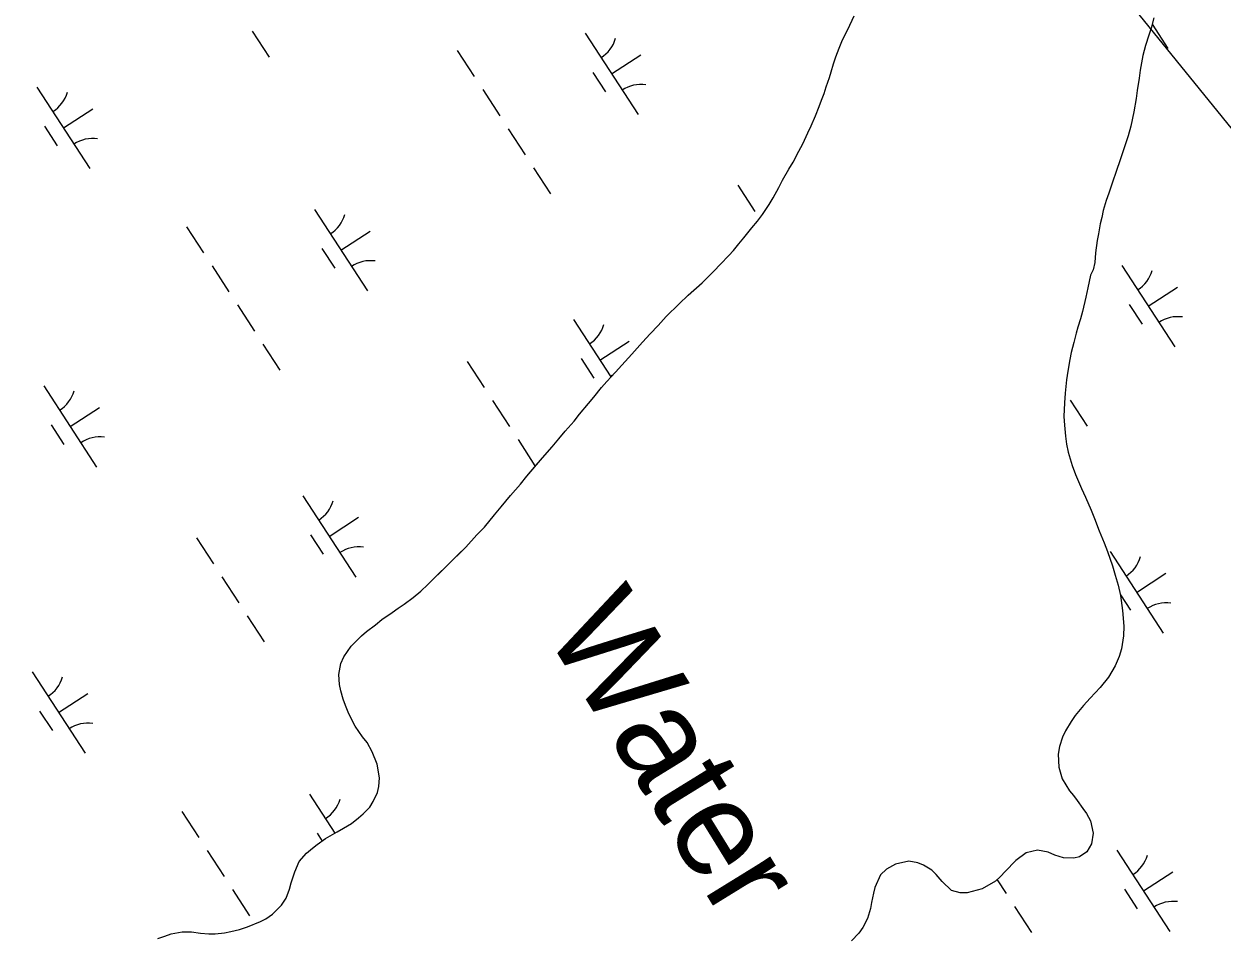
# Model space of a CAD drawing. Extents: x 3953924 to 3974542, y 193747 to 216192.
# Drawn here: x 3962480 to 3963097, y 211218 to 211687 of the extents above; entities that cross this region are included whole.
import ezdxf

# ---------------------------------------------------------------- set-up
doc = ezdxf.new("R2010")
doc.units = 0
for name, color, linetype in [('V-GRID-MAJR', 7, 'Continuous'), ('V-RIVR-IDEN', 7, 'Continuous'), ('V-TOPO-SHOR', 7, 'Continuous'), ('V-UTIL-LINE', 7, 'Continuous'), ('V-WETL-SWMP', 7, 'Continuous')]:
    doc.layers.add(name, color=color, linetype=linetype)

msp = doc.modelspace()

# ---------------------------------------------------------------- linework, layer by layer
at = {"layer": 'V-GRID-MAJR'}
msp.add_spline([(3962589.82, 201207.1), (3962493.71, 206368.64), (3962380.88, 212428.56), (3962369.25, 213053.16)], degree=3, dxfattribs=at)
at = {"layer": 'V-TOPO-SHOR'}
for points in [[(3962864.13, 211594.33), (3962866.18, 211597.83), (3962869.06, 211603.21), (3962870.97, 211606.98), (3962874.12, 211612.49), (3962876.45, 211616.25), (3962879.33, 211621.76), (3962881.38, 211625.66), (3962883.99, 211631.32), (3962885.77, 211634.95), (3962887.97, 211640.06), (3962889.77, 211644.91), (3962891, 211648.14), (3962892.38, 211651.51), (3962893.35, 211655.01), (3962895.15, 211659.72), (3962895.98, 211662.68), (3962897.22, 211666.73), (3962898.33, 211670.36), (3962900.12, 211674.8), (3962901.91, 211679.11), (3962904.52, 211684.49), (3962907.81, 211691.49)], [(3963062.14, 211690.44), (3963060.75, 211685.19), (3963059.5, 211681.55), (3963057.84, 211676.3), (3963056.45, 211671.04), (3963055.75, 211667.4), (3963055.04, 211663.63), (3963054.61, 211659.44), (3963053.62, 211653.1), (3963053.04, 211648.92), (3963051.91, 211642.05), (3963050.23, 211634.77), (3963048.98, 211629.78), (3963046.49, 211622.51), (3963044.97, 211617.93), (3963042.62, 211610.79), (3963041.1, 211606.35), (3963038.9, 211600.15), (3963037.65, 211596.38), (3963036.13, 211591.26), (3963035.29, 211587.76), (3963034.59, 211584.39), (3963033.6, 211579.26), (3963033.04, 211575.76), (3963032.18, 211569.42), (3963031.74, 211564.56), (3963030.9, 211560.79), (3963029.52, 211557.96), (3963028.12, 211551.49), (3963027.14, 211546.64), (3963025.47, 211539.36), (3963024.36, 211535.59), (3963022.98, 211531.14), (3963022.14, 211528.18), (3963020.89, 211523.33)], [(3962549.32, 211216.38), (3962552.98, 211217.7), (3962556.23, 211218.76), (3962561.77, 211219.8), (3962566.63, 211219.89), (3962571.22, 211219.18), (3962575.53, 211218.88), (3962578.78, 211218.86), (3962583.64, 211219.36), (3962586.89, 211220.01), (3962591.35, 211221.05), (3962595.54, 211222.37), (3962602.18, 211225.15), (3962604.89, 211226.49), (3962608.29, 211229.02), (3962612.91, 211233.58), (3962615.37, 211237.21), (3962617.03, 211241.92), (3962618, 211245.02), (3962619.8, 211250.81), (3962622.13, 211256.06), (3962625.81, 211260.35), (3962628.94, 211262.89), (3962631.38, 211264.77), (3962635.59, 211267.84), (3962641.69, 211271.3), (3962644.81, 211273.17), (3962649.02, 211275.7), (3962652.69, 211278.64), (3962655, 211280.65), (3962658.4, 211284.14), (3962660.18, 211286.96), (3962662.37, 211291.53), (3962663.07, 211294.63), (3962663.51, 211299.22), (3962662.21, 211306.25), (3962659.7, 211312.48), (3962657.04, 211317.36), (3962654.76, 211320.35), (3962650.89, 211325.78), (3962647.7, 211332.15), (3962645.97, 211336.35), (3962644.78, 211339.6), (3962643.47, 211343.93), (3962642.81, 211347.18), (3962642.45, 211352.31), (3962643.57, 211357.97), (3962645.09, 211361.47), (3962648.91, 211366.98), (3962654.21, 211372.21), (3962656.8, 211374.48), (3962661.42, 211377.96), (3962664.68, 211380.63), (3962669.97, 211384.37), (3962672.96, 211386.51), (3962676.21, 211388.51), (3962680.83, 211391.98), (3962684.64, 211395.2), (3962688.31, 211398.68), (3962693.89, 211404.17), (3962697.83, 211408.06), (3962703.82, 211413.95), (3962707.9, 211417.97), (3962713.62, 211424.27), (3962717.43, 211428.3), (3962722.61, 211434.6), (3962726.02, 211438.63), (3962730.92, 211444.53), (3962735.97, 211450.43), (3962739.24, 211454.46), (3962744.14, 211460.09), (3962747.41, 211463.85), (3962752.31, 211469.62), (3962755.72, 211473.64), (3962758.99, 211477.67), (3962763.62, 211482.76), (3962766.48, 211486.39), (3962770.98, 211491.89), (3962773.71, 211495.24), (3962777.66, 211500.21), (3962780.52, 211503.29), (3962784.88, 211508.12), (3962788.15, 211511.61), (3962793.32, 211517.24), (3962798.77, 211523.41), (3962802.86, 211527.83), (3962806.94, 211532.12), (3962811.02, 211536.68), (3962817.69, 211543.25), (3962822.45, 211547.67), (3962829.52, 211553.96), (3962835.64, 211560.12), (3962839.05, 211563.61), (3962843.27, 211568.17), (3962845.72, 211570.71), (3962848.44, 211574.2), (3962851.03, 211577.15), (3962855.12, 211582.39), (3962857.99, 211585.87), (3962860.71, 211589.23), (3962864.13, 211594.33)], [(3963020.89, 211523.33), (3963019.63, 211518.21), (3963018.93, 211514.56), (3963017.8, 211508.49), (3963017.23, 211504.05), (3963016.5, 211497.16), (3963016.2, 211492.31), (3963015.87, 211485.15), (3963016.11, 211480.69), (3963016.74, 211475.02), (3963017.25, 211470.96), (3963018.02, 211466.91), (3963020.13, 211460.01), (3963021.85, 211455.27), (3963024.9, 211448.22), (3963026.89, 211443.75), (3963029.81, 211436.98), (3963031.54, 211432.78), (3963034.05, 211426.41), (3963036.57, 211420.18), (3963038.29, 211415.71), (3963040.94, 211408.4), (3963042.25, 211403.53), (3963043.83, 211398.38), (3963045, 211393.11), (3963046.02, 211385.27), (3963046.77, 211377.3), (3963046.6, 211372.3), (3963045.47, 211365.56), (3963044.23, 211361.65), (3963042.16, 211356.81), (3963038.74, 211351.03), (3963034.52, 211345.66), (3963029.34, 211340.17), (3963025.94, 211336.41), (3963021.58, 211331.31), (3963019.53, 211328.22), (3963016.65, 211323.39), (3963015.15, 211320.15), (3963013.49, 211315.31), (3963012.92, 211311.4), (3963013.27, 211304.64), (3963014.98, 211298.69), (3963018.71, 211292.45), (3963020.72, 211290), (3963022.73, 211287.42), (3963025.67, 211283.35), (3963027.54, 211280.77), (3963029.53, 211276.97), (3963030.97, 211270.75), (3963030.12, 211265.22), (3963027.65, 211261.05), (3963023.85, 211258.52), (3963020.88, 211257.73), (3963015.61, 211257.9), (3963011.17, 211259.42), (3963007.81, 211260.93), (3963002.28, 211261.92), (3962996.46, 211260.48), (3962991.03, 211256.61), (3962985.58, 211250.98), (3962983.27, 211248.43), (3962980.55, 211245.88), (3962973.77, 211242.02), (3962966.06, 211239.92), (3962962.41, 211239.95), (3962957.96, 211241.2), (3962953.14, 211245.83), (3962950.06, 211249.36), (3962947.78, 211251.67), (3962943.62, 211254.27), (3962940.66, 211255.37), (3962935.94, 211256.22), (3962929.17, 211254.65), (3962924.43, 211252.12), (3962921.43, 211249.17), (3962918.41, 211242.72), (3962917.72, 211239.75), (3962916.73, 211235.03), (3962916.17, 211231.8), (3962914.65, 211226.81), (3962912.31, 211222.11), (3962910.27, 211219.15), (3962906.46, 211215.26)]]:
    msp.add_lwpolyline(points, dxfattribs=at)
at = {"layer": 'V-UTIL-LINE'}
msp.add_lwpolyline([(3962483.03, 212396.34), (3965459.79, 208729.14)], dxfattribs=at)
at = {"layer": 'V-WETL-SWMP'}
for p, q in [((3962904.52, 211684.49), (3962907.81, 211691.49)), ((3963062.14, 211690.44), (3963060.75, 211685.19)), ((3963061.3, 211687.26), (3963069.42, 211674.78)), ((3962597.86, 211683.61), (3962606.59, 211670.2)), ((3962769.32, 211682.56), (3962796.59, 211640.65)), ((3962901.91, 211679.11), (3962904.52, 211684.49)), ((3963059.5, 211681.55), (3963057.84, 211676.3)), ((3963060.75, 211685.19), (3963059.5, 211681.55)), ((3962703.5, 211673.62), (3962712.23, 211660.21)), ((3962898.33, 211670.36), (3962900.12, 211674.8)), ((3962900.12, 211674.8), (3962901.91, 211679.11)), ((3963057.84, 211676.3), (3963056.45, 211671.04)), ((3962782.96, 211661.6), (3962798.04, 211671.42)), ((3962897.22, 211666.73), (3962898.33, 211670.36)), ((3963055.75, 211667.4), (3963055.04, 211663.63)), ((3963056.45, 211671.04), (3963055.75, 211667.4)), ((3962773.22, 211662.42), (3962779.76, 211652.37)), ((3962895.14, 211659.72), (3962895.98, 211662.68)), ((3962895.98, 211662.68), (3962897.22, 211666.73)), ((3963055.04, 211663.63), (3963054.61, 211659.44)), ((3962487.02, 211654.77), (3962514.3, 211612.87)), ((3962892.38, 211651.51), (3962893.35, 211655.01)), ((3962893.35, 211655.01), (3962895.14, 211659.72)), ((3963054.61, 211659.44), (3963053.61, 211653.11)), ((3962716.59, 211653.51), (3962725.32, 211640.1)), ((3962891, 211648.14), (3962892.38, 211651.51)), ((3963053.04, 211648.92), (3963051.91, 211642.05)), ((3963053.61, 211653.11), (3963053.04, 211648.92)), ((3962500.66, 211633.82), (3962515.75, 211643.64)), ((3962887.97, 211640.06), (3962889.76, 211644.91)), ((3962889.76, 211644.91), (3962891, 211648.14)), ((3962885.77, 211634.95), (3962887.97, 211640.06)), ((3963051.91, 211642.05), (3963050.23, 211634.77)), ((3962490.92, 211634.64), (3962497.47, 211624.58)), ((3962729.68, 211633.4), (3962738.41, 211619.99)), ((3962881.38, 211625.66), (3962883.99, 211631.32)), ((3962883.99, 211631.32), (3962885.77, 211634.95)), ((3963050.23, 211634.77), (3963048.98, 211629.78)), ((3962879.33, 211621.76), (3962881.38, 211625.66)), ((3963048.98, 211629.78), (3963046.49, 211622.51)), ((3962876.45, 211616.25), (3962879.33, 211621.76)), ((3963044.97, 211617.93), (3963042.62, 211610.79)), ((3963046.49, 211622.51), (3963044.97, 211617.93)), ((3962742.78, 211613.28), (3962751.51, 211599.87)), ((3962870.98, 211606.98), (3962874.12, 211612.49)), ((3962874.12, 211612.49), (3962876.45, 211616.25)), ((3962869.06, 211603.21), (3962870.98, 211606.98)), ((3963041.1, 211606.35), (3963038.9, 211600.15)), ((3963042.62, 211610.79), (3963041.1, 211606.35)), ((3962847.98, 211604.26), (3962856.71, 211590.85)), ((3962866.18, 211597.83), (3962869.06, 211603.21)), ((3963038.9, 211600.15), (3963037.65, 211596.38)), ((3962860.71, 211589.23), (3962864.13, 211594.33)), ((3962864.13, 211594.33), (3962866.18, 211597.83)), ((3963037.65, 211596.38), (3963036.13, 211591.26)), ((3962629.91, 211591.81), (3962657.19, 211549.91)), ((3962857.99, 211585.87), (3962860.71, 211589.23)), ((3963035.29, 211587.76), (3963034.59, 211584.39)), ((3963036.13, 211591.26), (3963035.29, 211587.76)), ((3962564.09, 211582.88), (3962572.82, 211569.47)), ((3962851.03, 211577.15), (3962855.12, 211582.39)), ((3962855.12, 211582.39), (3962857.99, 211585.87)), ((3963034.59, 211584.39), (3963033.6, 211579.26)), ((3962643.55, 211570.86), (3962658.64, 211580.68)), ((3962848.45, 211574.2), (3962851.03, 211577.15)), ((3963033.04, 211575.76), (3963032.18, 211569.42)), ((3963033.6, 211579.26), (3963033.04, 211575.76)), ((3962633.81, 211571.68), (3962640.36, 211561.62)), ((3962843.27, 211568.17), (3962845.72, 211570.71)), ((3962845.72, 211570.71), (3962848.45, 211574.2)), ((3963032.18, 211569.42), (3963031.74, 211564.56)), ((3962577.19, 211562.76), (3962585.91, 211549.36)), ((3962835.64, 211560.12), (3962839.05, 211563.61)), ((3962839.05, 211563.61), (3962843.27, 211568.17)), ((3963031.74, 211564.56), (3963030.9, 211560.79)), ((3963045.63, 211562.98), (3963072.91, 211521.08)), ((3962829.52, 211553.96), (3962835.64, 211560.12)), ((3963029.52, 211557.96), (3963028.12, 211551.49)), ((3963030.9, 211560.79), (3963029.52, 211557.96)), ((3962822.45, 211547.67), (3962829.52, 211553.96)), ((3963028.12, 211551.49), (3963027.14, 211546.64)), ((3963059.27, 211542.03), (3963074.35, 211551.85)), ((3962817.69, 211543.25), (3962822.45, 211547.67)), ((3963027.14, 211546.64), (3963025.47, 211539.36)), ((3962590.28, 211542.65), (3962599.01, 211529.24)), ((3962811.02, 211536.68), (3962817.69, 211543.25)), ((3963025.47, 211539.36), (3963024.36, 211535.59)), ((3963049.53, 211542.85), (3963056.07, 211532.79)), ((3962763.33, 211535.19), (3962782.6, 211505.6)), ((3962802.85, 211527.83), (3962806.94, 211532.12)), ((3962806.94, 211532.12), (3962811.02, 211536.68)), ((3963024.36, 211535.59), (3963022.97, 211531.14)), ((3962798.77, 211523.41), (3962802.85, 211527.83)), ((3963022.14, 211528.18), (3963020.89, 211523.33)), ((3963022.97, 211531.14), (3963022.14, 211528.18)), ((3962603.37, 211522.54), (3962612.1, 211509.13)), ((3962776.97, 211514.24), (3962792.06, 211524.06)), ((3962793.32, 211517.24), (3962798.77, 211523.41)), ((3963020.89, 211523.33), (3963019.63, 211518.2)), ((3962708.58, 211513.52), (3962717.31, 211500.11)), ((3962767.23, 211515.06), (3962773.78, 211505)), ((3962788.15, 211511.61), (3962793.32, 211517.24)), ((3963018.93, 211514.56), (3963017.8, 211508.5)), ((3963019.63, 211518.2), (3963018.93, 211514.56)), ((3962780.52, 211503.29), (3962784.88, 211508.12)), ((3962784.88, 211508.12), (3962788.15, 211511.61)), ((3963017.8, 211508.5), (3963017.23, 211504.04)), ((3962490.51, 211501.07), (3962517.79, 211459.16)), ((3962777.66, 211500.21), (3962780.52, 211503.29)), ((3963017.23, 211504.04), (3963016.5, 211497.16)), ((3962770.98, 211491.89), (3962773.71, 211495.24)), ((3962773.71, 211495.24), (3962777.66, 211500.21)), ((3963016.5, 211497.16), (3963016.2, 211492.3)), ((3962504.15, 211480.11), (3962519.23, 211489.93)), ((3962721.67, 211493.4), (3962730.4, 211479.99)), ((3962766.49, 211486.39), (3962770.98, 211491.89)), ((3963016.2, 211492.3), (3963015.87, 211485.15)), ((3963019.09, 211493.71), (3963027.82, 211480.3)), ((3962758.99, 211477.67), (3962763.62, 211482.76)), ((3962763.62, 211482.76), (3962766.49, 211486.39)), ((3963015.87, 211485.15), (3963016.11, 211480.69)), ((3962494.41, 211480.93), (3962500.95, 211470.88)), ((3962755.72, 211473.64), (3962758.99, 211477.67)), ((3963016.11, 211480.69), (3963016.74, 211475.02)), ((3962734.76, 211473.29), (3962743.49, 211459.88)), ((3962752.31, 211469.62), (3962755.72, 211473.64)), ((3963016.74, 211475.02), (3963017.25, 211470.96)), ((3963017.25, 211470.96), (3963018.02, 211466.91)), ((3962739.24, 211454.46), (3962747.41, 211463.85)), ((3962747.41, 211463.85), (3962752.31, 211469.62)), ((3963018.02, 211466.91), (3963020.13, 211460)), ((3963020.13, 211460), (3963021.85, 211455.27)), ((3962735.96, 211450.43), (3962739.24, 211454.46)), ((3963021.85, 211455.27), (3963024.9, 211448.22)), ((3962730.92, 211444.53), (3962735.96, 211450.43)), ((3963024.9, 211448.22), (3963026.9, 211443.75)), ((3962623.93, 211444.45), (3962651.21, 211402.55)), ((3962726.02, 211438.63), (3962730.92, 211444.53)), ((3963026.9, 211443.75), (3963029.81, 211436.98)), ((3962637.57, 211423.5), (3962652.65, 211433.32)), ((3962717.43, 211428.3), (3962722.61, 211434.6)), ((3962722.61, 211434.6), (3962726.02, 211438.63)), ((3963029.81, 211436.98), (3963031.54, 211432.78)), ((3963031.54, 211432.78), (3963034.05, 211426.41)), ((3962713.62, 211424.27), (3962717.43, 211428.3)), ((3962569.17, 211422.77), (3962577.9, 211409.36)), ((3962627.83, 211424.32), (3962634.38, 211414.26)), ((3962707.9, 211417.97), (3962713.62, 211424.27)), ((3963034.05, 211426.41), (3963036.57, 211420.18)), ((3962688.31, 211398.68), (3962707.9, 211417.97)), ((3963036.57, 211420.18), (3963038.29, 211415.71)), ((3963038.29, 211415.71), (3963040.94, 211408.4)), ((3963039.64, 211415.62), (3963066.92, 211373.71)), ((3963040.94, 211408.4), (3963042.25, 211403.53)), ((3962582.27, 211402.66), (3962591, 211389.25)), ((3963042.25, 211403.53), (3963043.83, 211398.39)), ((3963053.28, 211394.67), (3963068.37, 211404.49)), ((3962684.64, 211395.2), (3962688.31, 211398.68)), ((3963043.83, 211398.39), (3963045, 211393.11)), ((3962676.21, 211388.51), (3962680.83, 211391.99)), ((3962680.83, 211391.99), (3962684.64, 211395.2)), ((3963044.96, 211393.31), (3963050.09, 211385.43)), ((3963045, 211393.11), (3963046.02, 211385.27)), ((3962664.68, 211380.63), (3962669.97, 211384.37)), ((3962669.97, 211384.37), (3962672.96, 211386.51)), ((3962672.96, 211386.51), (3962676.21, 211388.51)), ((3963046.02, 211385.27), (3963046.77, 211377.3)), ((3962595.36, 211382.54), (3962604.09, 211369.13)), ((3962656.8, 211374.48), (3962661.42, 211377.96)), ((3962661.42, 211377.96), (3962664.68, 211380.63)), ((3963046.77, 211377.3), (3963046.6, 211372.3)), ((3962648.91, 211366.98), (3962654.21, 211372.21)), ((3962654.21, 211372.21), (3962656.8, 211374.48)), ((3963046.6, 211372.3), (3963045.47, 211365.56)), ((3962645.08, 211361.47), (3962648.91, 211366.98)), ((3963045.47, 211365.56), (3963044.22, 211361.65)), ((3962643.57, 211357.97), (3962645.08, 211361.47)), ((3963044.22, 211361.65), (3963042.16, 211356.81)), ((3962484.53, 211353.71), (3962511.8, 211311.8)), ((3962642.45, 211352.31), (3962643.57, 211357.97)), ((3963042.16, 211356.81), (3963038.74, 211351.03)), ((3962642.81, 211347.18), (3962642.45, 211352.31)), ((3962643.47, 211343.93), (3962642.81, 211347.18)), ((3963038.74, 211351.03), (3963034.52, 211345.66)), ((3962498.16, 211332.75), (3962513.25, 211342.57)), ((3962644.78, 211339.6), (3962643.47, 211343.93)), ((3963029.34, 211340.16), (3963025.94, 211336.41)), ((3963034.52, 211345.66), (3963029.34, 211340.16)), ((3962645.97, 211336.35), (3962644.78, 211339.6)), ((3962647.7, 211332.15), (3962645.97, 211336.35)), ((3963025.94, 211336.41), (3963021.58, 211331.31)), ((3962488.42, 211333.57), (3962494.97, 211323.52)), ((3962650.89, 211325.78), (3962647.7, 211332.15)), ((3963019.53, 211328.22), (3963016.66, 211323.38)), ((3963021.58, 211331.31), (3963019.53, 211328.22)), ((3962654.76, 211320.35), (3962650.89, 211325.78)), ((3963016.66, 211323.38), (3963015.15, 211320.15)), ((3962657.04, 211317.36), (3962654.76, 211320.35)), ((3962659.7, 211312.48), (3962657.04, 211317.36)), ((3963015.15, 211320.15), (3963013.49, 211315.31)), ((3962662.22, 211306.25), (3962659.7, 211312.48)), ((3963013.49, 211315.31), (3963012.92, 211311.4)), ((3963012.92, 211311.4), (3963013.27, 211304.64)), ((3962663.51, 211299.22), (3962662.22, 211306.25)), ((3963013.27, 211304.64), (3963014.98, 211298.69)), ((3962663.07, 211294.63), (3962663.51, 211299.22)), ((3963014.98, 211298.69), (3963018.71, 211292.45)), ((3962660.18, 211286.96), (3962662.37, 211291.53)), ((3962662.37, 211291.53), (3962663.07, 211294.63)), ((3963018.71, 211292.45), (3963020.72, 211290)), ((3962627.42, 211290.75), (3962640.51, 211270.63)), ((3962658.4, 211284.14), (3962660.18, 211286.96)), ((3963020.72, 211290), (3963022.73, 211287.42)), ((3963022.73, 211287.42), (3963025.67, 211283.35)), ((3962561.6, 211281.81), (3962570.32, 211268.4)), ((3962649.02, 211275.7), (3962652.69, 211278.64)), ((3962652.69, 211278.64), (3962655, 211280.65)), ((3962655, 211280.65), (3962658.4, 211284.14)), ((3963025.67, 211283.35), (3963027.54, 211280.77)), ((3963027.54, 211280.77), (3963029.53, 211276.97)), ((3962641.69, 211271.3), (3962644.81, 211273.17)), ((3962644.81, 211273.17), (3962649.02, 211275.7)), ((3963029.53, 211276.97), (3963030.97, 211270.75)), ((3962631.31, 211270.61), (3962633.92, 211266.62)), ((3962631.38, 211264.76), (3962635.59, 211267.84)), ((3962635.59, 211267.84), (3962641.69, 211271.3)), ((3963030.97, 211270.75), (3963030.12, 211265.22)), ((3962574.69, 211261.7), (3962583.42, 211248.29)), ((3962622.13, 211256.06), (3962625.81, 211260.35)), ((3962625.81, 211260.35), (3962628.94, 211262.89)), ((3962628.94, 211262.89), (3962631.38, 211264.76)), ((3962996.46, 211260.48), (3962991.03, 211256.61)), ((3963002.28, 211261.92), (3962996.46, 211260.48)), ((3963007.81, 211260.93), (3963002.28, 211261.92)), ((3963011.17, 211259.42), (3963007.81, 211260.93)), ((3963027.66, 211261.05), (3963023.85, 211258.52)), ((3963030.12, 211265.22), (3963027.66, 211261.05)), ((3963043.13, 211261.92), (3963070.41, 211220.01)), ((3962619.8, 211250.81), (3962622.13, 211256.06)), ((3962929.17, 211254.65), (3962924.43, 211252.12)), ((3962935.94, 211256.22), (3962929.17, 211254.65)), ((3962940.66, 211255.37), (3962935.94, 211256.22)), ((3962943.62, 211254.27), (3962940.66, 211255.37)), ((3962947.78, 211251.67), (3962943.62, 211254.27)), ((3962991.03, 211256.61), (3962985.58, 211250.98)), ((3963015.61, 211257.9), (3963011.17, 211259.42)), ((3963020.88, 211257.73), (3963015.61, 211257.9)), ((3963023.85, 211258.52), (3963020.88, 211257.73)), ((3962618, 211245.02), (3962619.8, 211250.81)), ((3962921.43, 211249.17), (3962918.41, 211242.72)), ((3962924.43, 211252.12), (3962921.43, 211249.17)), ((3962950.06, 211249.36), (3962947.78, 211251.67)), ((3962953.14, 211245.83), (3962950.06, 211249.36)), ((3962983.27, 211248.43), (3962980.55, 211245.89)), ((3962985.58, 211250.98), (3962983.27, 211248.43)), ((3963056.77, 211240.96), (3963071.85, 211250.78)), ((3962587.78, 211241.59), (3962596.51, 211228.18)), ((3962615.37, 211237.21), (3962617.03, 211241.92)), ((3962617.03, 211241.92), (3962618, 211245.02)), ((3962918.41, 211242.72), (3962917.72, 211239.75)), ((3962957.96, 211241.2), (3962953.14, 211245.83)), ((3962973.77, 211242.02), (3962966.06, 211239.92)), ((3962980.55, 211245.89), (3962973.77, 211242.02)), ((3962981.41, 211246.69), (3962986.04, 211239.57)), ((3963047.03, 211241.78), (3963053.58, 211231.73)), ((3962612.91, 211233.58), (3962615.37, 211237.21)), ((3962917.72, 211239.75), (3962916.73, 211235.03)), ((3962962.41, 211239.95), (3962957.96, 211241.2)), ((3962966.06, 211239.92), (3962962.41, 211239.95)), ((3962608.29, 211229.02), (3962612.91, 211233.58)), ((3962916.17, 211231.8), (3962914.65, 211226.81)), ((3962916.73, 211235.03), (3962916.17, 211231.8)), ((3962990.4, 211232.87), (3962999.13, 211219.46)), ((3962595.54, 211222.37), (3962602.18, 211225.15)), ((3962602.18, 211225.15), (3962604.89, 211226.49)), ((3962604.89, 211226.49), (3962608.29, 211229.02)), ((3962914.65, 211226.81), (3962912.31, 211222.1)), ((3962552.98, 211217.7), (3962556.23, 211218.76)), ((3962556.23, 211218.76), (3962561.77, 211219.79)), ((3962561.77, 211219.79), (3962566.63, 211219.89)), ((3962566.63, 211219.89), (3962571.22, 211219.18)), ((3962571.22, 211219.18), (3962575.53, 211218.88)), ((3962575.53, 211218.88), (3962578.77, 211218.85)), ((3962578.77, 211218.85), (3962583.64, 211219.36)), ((3962583.64, 211219.36), (3962586.89, 211220.01)), ((3962586.89, 211220.01), (3962591.35, 211221.05)), ((3962591.35, 211221.05), (3962595.54, 211222.37)), ((3962910.27, 211219.15), (3962906.46, 211215.26)), ((3962912.31, 211222.1), (3962910.27, 211219.15))]:
    msp.add_line(p, q, dxfattribs=at)
for centre, start, end in [((3962768.09, 211684.88), 302.29009, 343.83375), ((3962798.22, 211638.58), 82.29009, 123.83375), ((3962485.79, 211657.1), 302.29009, 343.83375), ((3962515.93, 211610.8), 82.29009, 123.83375), ((3962628.68, 211594.14), 302.29009, 343.83375), ((3962658.82, 211547.84), 82.29009, 123.83375), ((3963044.4, 211565.31), 302.29009, 343.83375), ((3962762.1, 211537.52), 302.29009, 343.83375), ((3963074.53, 211519.01), 82.29009, 123.83375), ((3962792.24, 211491.22), 120.19294, 123.83375), ((3962489.28, 211503.39), 302.29009, 343.83375), ((3962519.41, 211457.09), 82.29009, 123.83375), ((3962622.7, 211446.78), 302.29009, 343.83375), ((3962652.84, 211400.48), 82.29009, 123.83375), ((3963038.41, 211417.95), 302.29009, 343.83375), ((3963068.55, 211371.65), 82.29009, 123.83375), ((3962483.29, 211356.03), 302.29009, 343.83375), ((3962513.43, 211309.73), 82.29009, 123.83375), ((3962626.18, 211293.07), 302.29009, 343.83375), ((3963041.9, 211264.24), 302.29009, 343.83375), ((3963072.04, 211217.94), 82.29009, 123.83375)]:
    msp.add_arc(centre, 17.62, start, end, dxfattribs=at)

# ---------------------------------------------------------------- texts
at = {"layer": 'V-RIVR-IDEN'}
msp.add_text('Water', height=50, rotation=301.66125, dxfattribs=at).set_placement((3962747.68, 211375.14))

doc.saveas('drawing.dxf')
